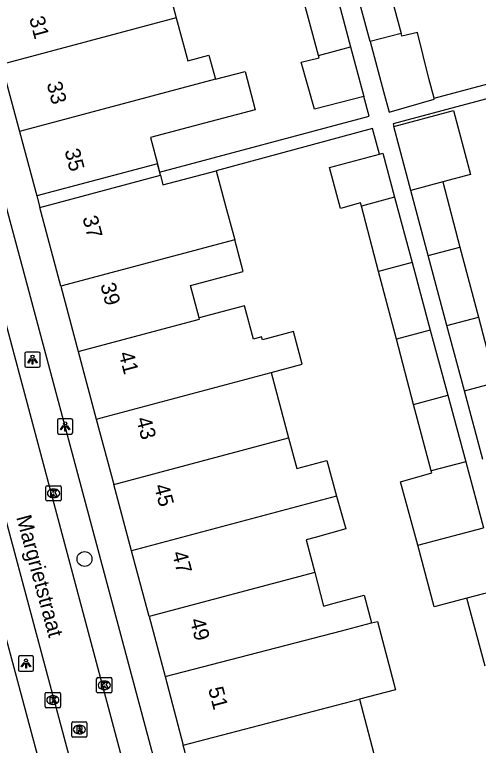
# Model space of a CAD drawing. Extents: x 162542 to 163144, y 380786 to 381511.
# Drawn here: x 162891.48 to 162921.91, y 380943.84 to 380991.8 of the extents above; entities that cross this region are included whole.
import ezdxf

# ---------------------------------------------------------------- set-up
doc = ezdxf.new("R2010")
doc.units = 0
for name, color, linetype in [('IMGEO_Boom', 7, 'Continuous'), ('IMGEO_Kolk', 7, 'Continuous'), ('IMGEO_Lichtpunt', 7, 'Continuous'), ('IMGEO_Openbare_ruimte_label', 7, 'Continuous'), ('IMGEO_Pand', 7, 'Continuous'), ('IMGEO_Pand_nummerreeks', 7, 'Continuous'), ('IMGEO_Pand_overbouw', 7, 'Continuous'), ('IMGEO_Rijbaan_lokaal_open', 7, 'Continuous'), ('IMGEO_Rioolput', 7, 'Continuous'), ('IMGEO_Voetpad_open', 7, 'Continuous')]:
    doc.layers.add(name, color=color, linetype=linetype)

msp = doc.modelspace()

# ---------------------------------------------------------------- linework, layer by layer
at = {"layer": 'IMGEO_Boom'}
msp.add_circle((162896.066, 380956.069), 0.489, dxfattribs=at)
at = {"layer": 'IMGEO_Kolk'}
for p, q in [((162893.609, 380960.881), (162894.461, 380960.881)), ((162893.534, 380959.955), (162893.534, 380960.807)), ((162894.022, 380960.661), (162894.047, 380960.661)), ((162894.535, 380960.807), (162894.535, 380959.955)), ((162894.045, 380960.101), (162894.02, 380960.101)), ((162894.461, 380959.881), (162893.609, 380959.881)), ((162896.863, 380947.355), (162896.863, 380948.207)), ((162896.938, 380948.281), (162897.79, 380948.281)), ((162897.351, 380948.061), (162897.376, 380948.061)), ((162897.864, 380948.207), (162897.864, 380947.355)), ((162897.374, 380947.501), (162897.349, 380947.501)), ((162893.489, 380946.382), (162893.489, 380947.234)), ((162893.564, 380947.308), (162894.416, 380947.308)), ((162893.977, 380947.088), (162894.002, 380947.088)), ((162894.49, 380947.234), (162894.49, 380946.382)), ((162897.79, 380947.281), (162896.938, 380947.281)), ((162894, 380946.528), (162893.975, 380946.528)), ((162894.416, 380946.308), (162893.564, 380946.308))]:
    msp.add_line(p, q, dxfattribs=at)
for points in [[(162893.609, 380960.881), (162894.461, 380960.881)], [(162893.534, 380959.955), (162893.534, 380960.807)], [(162893.855, 380960.581), (162893.978, 380960.581), (162893.978, 380960.43), (162894.108, 380960.581), (162894.272, 380960.581), (162894.126, 380960.43), (162894.279, 380960.181), (162894.127, 380960.181), (162894.042, 380960.345), (162893.978, 380960.278), (162893.978, 380960.181), (162893.855, 380960.181), (162893.855, 380960.581)], [(162894.535, 380960.807), (162894.535, 380959.955)], [(162894.461, 380959.881), (162893.609, 380959.881)], [(162896.863, 380947.355), (162896.863, 380948.207)], [(162896.938, 380948.281), (162897.79, 380948.281)], [(162897.184, 380947.981), (162897.307, 380947.981), (162897.307, 380947.83), (162897.437, 380947.981), (162897.601, 380947.981), (162897.455, 380947.83), (162897.608, 380947.581), (162897.456, 380947.581), (162897.371, 380947.745), (162897.307, 380947.678), (162897.307, 380947.581), (162897.184, 380947.581), (162897.184, 380947.981)], [(162897.864, 380948.207), (162897.864, 380947.355)], [(162893.489, 380946.382), (162893.489, 380947.234)], [(162893.564, 380947.308), (162894.416, 380947.308)], [(162893.81, 380947.008), (162893.933, 380947.008), (162893.933, 380946.857), (162894.063, 380947.008), (162894.227, 380947.008), (162894.081, 380946.857), (162894.234, 380946.608), (162894.082, 380946.608), (162893.997, 380946.772), (162893.933, 380946.705), (162893.933, 380946.608), (162893.81, 380946.608), (162893.81, 380947.008)], [(162894.49, 380947.234), (162894.49, 380946.382)], [(162897.79, 380947.281), (162896.938, 380947.281)], [(162894.416, 380946.308), (162893.564, 380946.308)]]:
    msp.add_lwpolyline(points, dxfattribs=at)
for centre, start, end in [((162893.611, 380960.805), 91.552, 178.448), ((162893.611, 380960.805), 91.552, 178.448), ((162894.459, 380960.805), 1.552, 88.448), ((162894.459, 380960.805), 1.552, 88.448), ((162893.611, 380959.957), 181.552, 268.448), ((162893.611, 380959.957), 181.552, 268.448), ((162894.459, 380959.957), 271.552, 358.448), ((162894.459, 380959.957), 271.552, 358.448), ((162896.94, 380948.205), 91.552, 178.448), ((162896.94, 380948.205), 91.552, 178.448), ((162897.788, 380948.205), 1.552, 88.448), ((162897.788, 380948.205), 1.552, 88.448), ((162893.566, 380947.232), 91.552, 178.448), ((162893.566, 380947.232), 91.552, 178.448), ((162894.414, 380947.232), 1.552, 88.448), ((162894.414, 380947.232), 1.552, 88.448), ((162896.94, 380947.357), 181.552, 268.448), ((162896.94, 380947.357), 181.552, 268.448), ((162897.788, 380947.357), 271.552, 358.448), ((162897.788, 380947.357), 271.552, 358.448), ((162893.566, 380946.384), 181.552, 268.448), ((162893.566, 380946.384), 181.552, 268.448), ((162894.414, 380946.384), 271.552, 358.448), ((162894.414, 380946.384), 271.552, 358.448)]:
    msp.add_arc(centre, 0.0765, start, end, dxfattribs=at)
for centre, major_axis, ratio, start_param, end_param in [((162894.021, 380960.381), (-0.387, 0.002), 0.722429, 4.712389, 7.853982), ((162894.046, 380960.381), (-0.39, 0.002), 0.717154, 1.570796, 4.712389), ((162897.35, 380947.781), (-0.387, 0.002), 0.722429, 4.712389, 7.853982), ((162897.375, 380947.781), (-0.39, 0.002), 0.717154, 1.570796, 4.712389), ((162893.976, 380946.808), (-0.387, 0.002), 0.722429, 4.712389, 7.853982), ((162894.001, 380946.808), (-0.39, 0.002), 0.717154, 1.570796, 4.712389)]:
    msp.add_ellipse(centre, major_axis=major_axis, ratio=ratio, start_param=start_param, end_param=end_param, dxfattribs=at)
at = {"layer": 'IMGEO_Lichtpunt'}
for p, q in [((162892.155, 380969.558), (162892.155, 380968.751)), ((162892.155, 380969.558), (162892.155, 380968.751)), ((162893.057, 380969.653), (162892.249, 380969.653)), ((162893.057, 380969.653), (162892.249, 380969.653)), ((162893.151, 380968.751), (162893.151, 380969.558)), ((162893.151, 380968.751), (162893.151, 380969.558)), ((162892.249, 380968.657), (162893.057, 380968.657)), ((162892.249, 380968.657), (162893.057, 380968.657)), ((162895.2, 380965.271), (162894.392, 380965.271)), ((162895.2, 380965.271), (162894.392, 380965.271)), ((162894.298, 380965.176), (162894.298, 380964.369)), ((162894.298, 380965.176), (162894.298, 380964.369)), ((162895.294, 380964.369), (162895.294, 380965.176)), ((162895.294, 380964.369), (162895.294, 380965.176)), ((162894.392, 380964.275), (162895.2, 380964.275)), ((162894.392, 380964.275), (162895.2, 380964.275)), ((162891.73, 380949.612), (162891.73, 380948.805)), ((162891.73, 380949.612), (162891.73, 380948.805)), ((162892.632, 380949.707), (162891.824, 380949.707)), ((162892.632, 380949.707), (162891.824, 380949.707)), ((162892.726, 380948.805), (162892.726, 380949.612)), ((162892.726, 380948.805), (162892.726, 380949.612)), ((162891.824, 380948.711), (162892.632, 380948.711)), ((162891.824, 380948.711), (162892.632, 380948.711))]:
    msp.add_line(p, q, dxfattribs=at)
for points in [[(162892.529, 380969.222), (162892.568, 380969.194), (162892.38, 380968.932), (162892.342, 380968.959), (162892.529, 380969.222)], [(162892.631, 380969.174), (162892.678, 380969.174), (162892.678, 380968.852), (162892.631, 380968.852), (162892.631, 380969.174)], [(162892.741, 380969.194), (162892.779, 380969.221), (162892.966, 380968.959), (162892.927, 380968.931), (162892.741, 380969.194)], [(162894.672, 380964.84), (162894.711, 380964.812), (162894.523, 380964.55), (162894.485, 380964.577), (162894.672, 380964.84)], [(162894.774, 380964.792), (162894.821, 380964.792), (162894.821, 380964.47), (162894.774, 380964.47), (162894.774, 380964.792)], [(162894.884, 380964.812), (162894.922, 380964.839), (162895.109, 380964.577), (162895.07, 380964.549), (162894.884, 380964.812)], [(162892.104, 380949.276), (162892.143, 380949.248), (162891.955, 380948.986), (162891.917, 380949.013), (162892.104, 380949.276)], [(162892.206, 380949.228), (162892.253, 380949.228), (162892.253, 380948.906), (162892.206, 380948.906), (162892.206, 380949.228)], [(162892.316, 380949.248), (162892.354, 380949.275), (162892.541, 380949.013), (162892.502, 380948.985), (162892.316, 380949.248)]]:
    msp.add_lwpolyline(points, dxfattribs=at)
for centre in [(162892.654, 380969.356), (162894.797, 380964.974), (162892.229, 380949.41)]:
    msp.add_circle(centre, 0.0994, dxfattribs=at)
for centre, start, end in [((162892.249, 380969.558), 90, 180), ((162892.249, 380969.558), 90, 180), ((162893.057, 380969.558), 0, 90), ((162893.057, 380969.558), 0, 90), ((162892.249, 380968.751), 180, 270), ((162892.249, 380968.751), 180, 270), ((162893.057, 380968.751), 270, 0), ((162893.057, 380968.751), 270, 360), ((162894.392, 380965.176), 90, 180), ((162894.392, 380965.176), 90, 180), ((162895.2, 380965.176), 0, 90), ((162895.2, 380965.176), 0, 90), ((162894.392, 380964.369), 180, 270), ((162894.392, 380964.369), 180, 270), ((162895.2, 380964.369), 270, 0), ((162895.2, 380964.369), 270, 360), ((162891.824, 380949.612), 90, 180), ((162891.824, 380949.612), 90, 180), ((162892.632, 380949.612), 0, 90), ((162892.632, 380949.612), 0, 90), ((162891.824, 380948.805), 180, 270), ((162891.824, 380948.805), 180, 270), ((162892.632, 380948.805), 270, 0), ((162892.632, 380948.805), 270, 360)]:
    msp.add_arc(centre, 0.0946, start, end, dxfattribs=at)
at = {"layer": 'IMGEO_Pand'}
for points in [[(162900.934, 380995.873), (162902.089, 380991.591)], [(162915.691, 380994.881), (162916.846, 380990.574)], [(162912.376, 380993.998), (162913.53, 380989.691)], [(162914.813, 380990.033), (162913.656, 380994.339)], [(162911.42, 380989.13), (162910.258, 380993.435)], [(162902.089, 380991.591), (162890.629, 380988.534)], [(162902.089, 380991.591), (162902.85, 380988.772), (162904.225, 380989.143), (162904.653, 380987.557)], [(162919.001, 380986.33), (162918.664, 380987.611), (162917.921, 380990.636), (162916.893, 380990.399), (162916.846, 380990.574)], [(162916.846, 380990.574), (162914.813, 380990.033)], [(162911.42, 380989.13), (162913.53, 380989.691)], [(162913.53, 380989.691), (162914.405, 380986.427)], [(162914.813, 380990.033), (162915.692, 380986.763), (162916.056, 380985.411), (162919.02, 380986.257), (162919.001, 380986.33)], [(162914.405, 380986.427), (162911.166, 380985.607), (162910.272, 380988.688), (162911.464, 380988.965), (162911.42, 380989.13)], [(162890.629, 380988.534), (162891.804, 380984.13)], [(162904.653, 380987.557), (162906.602, 380988.077), (162907.272, 380985.564), (162903.947, 380984.678), (162900.387, 380983.729), (162900.845, 380982.011)], [(162904.653, 380987.557), (162891.804, 380984.13)], [(162916.367, 380984.462), (162920.286, 380985.507), (162921.393, 380981.311), (162919.572, 380980.826)], [(162917.486, 380980.266), (162916.367, 380984.462)], [(162891.804, 380984.13), (162892.932, 380979.9)], [(162914.231, 380979.241), (162914.178, 380979.441), (162912.863, 380979.087), (162912.141, 380981.771), (162915.42, 380982.652)], [(162915.42, 380982.652), (162915.634, 380982.71), (162916.411, 380979.823)], [(162900.845, 380982.011), (162892.932, 380979.9)], [(162893.132, 380979.151), (162901.045, 380981.262), (162901.214, 380980.628), (162904.712, 380981.561)], [(162904.712, 380981.561), (162905.328, 380979.254), (162905.923, 380977.025)], [(162919.572, 380980.826), (162917.486, 380980.266)], [(162919.572, 380980.826), (162920.703, 380976.529)], [(162918.627, 380975.99), (162917.486, 380980.266)], [(162916.411, 380979.823), (162914.231, 380979.241)], [(162916.411, 380979.823), (162917.565, 380975.53)], [(162894.511, 380973.981), (162893.132, 380979.151)], [(162915.364, 380974.943), (162914.231, 380979.241)], [(162905.923, 380977.025), (162894.511, 380973.981)], [(162903.587, 380971.9), (162903.021, 380974.02), (162906.479, 380974.942), (162905.923, 380977.025)], [(162918.627, 380975.99), (162920.703, 380976.529)], [(162920.703, 380976.529), (162921.91, 380971.941)], [(162919.852, 380971.394), (162918.627, 380975.99)], [(162917.565, 380975.53), (162915.364, 380974.943)], [(162917.565, 380975.53), (162918.756, 380971.102)], [(162916.533, 380970.509), (162915.364, 380974.943)], [(162894.511, 380973.981), (162895.656, 380969.686)], [(162908.309, 380968.315), (162910.353, 380968.86), (162909.782, 380970.998), (162907.736, 380970.452), (162907.684, 380970.648), (162907.146, 380970.505), (162906.562, 380972.693), (162903.587, 380971.9)], [(162895.656, 380969.686), (162903.611, 380971.808), (162903.587, 380971.9)], [(162919.852, 380971.394), (162921.91, 380971.941)], [(162921.91, 380971.941), (162923.04, 380967.646)], [(162918.756, 380971.102), (162916.533, 380970.509)], [(162918.756, 380971.102), (162919.909, 380966.814)], [(162920.997, 380967.102), (162919.852, 380971.394)], [(162917.665, 380966.215), (162916.533, 380970.509)], [(162895.656, 380969.686), (162896.838, 380965.255)], [(162896.838, 380965.255), (162908.309, 380968.315)], [(162908.309, 380968.315), (162909.459, 380964.026)], [(162920.997, 380967.102), (162923.04, 380967.646)], [(162922.195, 380962.611), (162920.997, 380967.102)], [(162917.665, 380966.215), (162919.909, 380966.814)], [(162919.909, 380966.814), (162921.081, 380962.458)], [(162918.814, 380961.854), (162917.665, 380966.215)], [(162896.838, 380965.255), (162897.983, 380960.964)], [(162897.983, 380960.964), (162909.459, 380964.026)], [(162909.459, 380964.026), (162909.999, 380962.012), (162911.967, 380962.537), (162912.597, 380960.195)], [(162921.081, 380962.458), (162918.814, 380961.854)], [(162921.081, 380962.458), (162922.248, 380958.118)], [(162917.929, 380956.97), (162916.808, 380961.131), (162918.85, 380961.719), (162918.814, 380961.854)], [(162899.145, 380956.607), (162897.983, 380960.964)], [(162912.597, 380960.195), (162899.145, 380956.607)], [(162912.597, 380960.195), (162913.21, 380958.051), (162911.208, 380957.479), (162910.608, 380957.319), (162911.173, 380955.175)], [(162917.929, 380956.97), (162922.248, 380958.118)], [(162900.298, 380952.285), (162899.145, 380956.607)], [(162921.158, 380953.498), (162919.014, 380952.941), (162917.929, 380956.97)], [(162911.173, 380955.175), (162900.298, 380952.285)], [(162911.173, 380955.175), (162911.751, 380952.982), (162912.448, 380953.168), (162914.415, 380953.693), (162914.896, 380951.87)], [(162923.338, 380954.064), (162921.158, 380953.498)], [(162922.36, 380949.028), (162921.158, 380953.498)], [(162900.298, 380952.285), (162901.348, 380948.349)], [(162901.348, 380948.349), (162912.925, 380951.358), (162914.896, 380951.87)], [(162914.896, 380951.87), (162915.302, 380951.976), (162916.475, 380947.489), (162914.108, 380946.87)], [(162901.348, 380948.349), (162902.548, 380943.847)], [(162902.548, 380943.847), (162914.108, 380946.87)], [(162914.108, 380946.87), (162915.273, 380942.447)], [(162903.739, 380939.382), (162902.548, 380943.847)]]:
    msp.add_lwpolyline(points, dxfattribs=at)
at = {"layer": 'IMGEO_Pand_overbouw'}
msp.add_lwpolyline([(162901.045, 380981.262), (162900.845, 380982.011), (162892.932, 380979.9), (162893.132, 380979.151)], close=True, dxfattribs=at)
at = {"layer": 'IMGEO_Rijbaan_lokaal_open'}
for points in [[(162901.876, 380930.848), (162901.838, 380930.972), (162901.555, 380931.634), (162890.133, 380974.374), (162888.386, 380980.871)], [(162898.286, 380931.049), (162885.174, 380980.018)]]:
    msp.add_lwpolyline(points, dxfattribs=at)
at = {"layer": 'IMGEO_Rioolput'}
for p, q in [((162895.226, 380944.449), (162895.226, 380945.301)), ((162895.301, 380945.375), (162896.153, 380945.375)), ((162895.714, 380945.155), (162895.739, 380945.155)), ((162896.227, 380945.301), (162896.227, 380944.449)), ((162895.737, 380944.595), (162895.712, 380944.595)), ((162896.153, 380944.375), (162895.301, 380944.375))]:
    msp.add_line(p, q, dxfattribs=at)
for points in [[(162895.226, 380944.449), (162895.226, 380945.301)], [(162895.301, 380945.375), (162896.153, 380945.375)], [(162895.815, 380945.073), (162895.563, 380945.075), (162895.563, 380944.675)], [(162896.227, 380945.301), (162896.227, 380944.449)], [(162895.563, 380944.675), (162895.687, 380944.675), (162895.687, 380944.837), (162895.698, 380944.837)], [(162895.741, 380944.994), (162895.687, 380944.994), (162895.687, 380944.913)], [(162895.687, 380944.913), (162895.739, 380944.913)], [(162895.745, 380944.808), (162895.816, 380944.675), (162895.956, 380944.675), (162895.891, 380944.801)], [(162896.153, 380944.375), (162895.301, 380944.375)]]:
    msp.add_lwpolyline(points, dxfattribs=at)
for centre, radius, start, end in [((162895.303, 380945.299), 0.0765, 91.552, 178.448), ((162895.303, 380945.299), 0.0765, 91.552, 178.448), ((162895.814, 380944.963), 0.109, 350.3612, 89.416), ((162896.151, 380945.299), 0.0765, 1.552, 88.448), ((162896.151, 380945.299), 0.0765, 1.552, 88.448), ((162895.697, 380944.784), 0.0533, 26.0293, 88.6989), ((162895.723, 380945.102), 0.19, 274.7715, 282.9687), ((162895.747, 380944.898), 0.0964, 77.0061, 93.1865), ((162895.761, 380944.955), 0.0378, 276.6634, 79.6772), ((162895.812, 380944.963), 0.112, 277.5842, 350.9817), ((162895.796, 380944.748), 0.108, 29.5134, 73.7905), ((162895.303, 380944.451), 0.0765, 181.552, 268.448), ((162895.303, 380944.451), 0.0765, 181.552, 268.448), ((162896.151, 380944.451), 0.0765, 271.552, 358.448), ((162896.151, 380944.451), 0.0765, 271.552, 358.448)]:
    msp.add_arc(centre, radius, start, end, dxfattribs=at)
for centre, major_axis, ratio, start_param, end_param in [((162895.713, 380944.875), (-0.387, 0.002), 0.722429, 4.712389, 7.853982), ((162895.738, 380944.875), (-0.39, 0.002), 0.717154, 1.570796, 4.712389)]:
    msp.add_ellipse(centre, major_axis=major_axis, ratio=ratio, start_param=start_param, end_param=end_param, dxfattribs=at)
at = {"layer": 'IMGEO_Voetpad_open'}
for points in [[(162903.319, 380932.863), (162892.108, 380974.822), (162879.625, 381021.207), (162879.415, 381022.016), (162879.319, 381022.406), (162879.144, 381023.334), (162876.936, 381034.701), (162876.741, 381035.545), (162876.464, 381036.645), (162868.265, 381067.311)], [(162902.951, 380908.79), (162898.843, 380924.15), (162898.786, 380924.4), (162898.683, 380924.706), (162897.228, 380928.095), (162896.835, 380929.036), (162896.579, 380929.758), (162896.332, 380930.722), (162882.251, 380983.223), (162872.201, 381021.07), (162869.619, 381033.902), (162863.623, 381056.326)], [(162919.001, 380986.33), (162929.567, 380989.141)], [(162926.238, 380987.285), (162916.32, 380984.64), (162916.367, 380984.462)], [(162900.845, 380982.011), (162900.989, 380981.472), (162914.751, 380985.14), (162914.405, 380986.427)], [(162915.42, 380982.652), (162914.972, 380984.319), (162904.712, 380981.561)], [(162892.932, 380979.9), (162893.132, 380979.151)]]:
    msp.add_lwpolyline(points, dxfattribs=at)

# ---------------------------------------------------------------- texts
at = {"layer": 'IMGEO_Openbare_ruimte_label'}
msp.add_text('Margrietstraat', height=1, rotation=285.1898, dxfattribs=at).set_placement((162891.575, 380958.813))
at = {"layer": 'IMGEO_Pand_nummerreeks'}
for s, rotation, p in [('31', 284.9344, (162892.428, 380991.567)), ('33', 284.9368, (162893.573, 380987.274)), ('35', 284.9368, (162894.747, 380982.872)), ('37', 284.9344, (162895.922, 380978.47)), ('39', 284.9368, (162897.095, 380974.068)), ('41', 284.9368, (162898.298, 380969.556)), ('43', 284.9344, (162899.444, 380965.264)), ('45', 284.9344, (162900.618, 380960.862)), ('47', 284.9344, (162901.793, 380956.46)), ('49', 284.9368, (162902.966, 380952.057)), ('51', 284.9368, (162904.169, 380947.545))]:
    msp.add_text(s, height=1, rotation=rotation, dxfattribs=at).set_placement(p)

doc.saveas('drawing.dxf')
